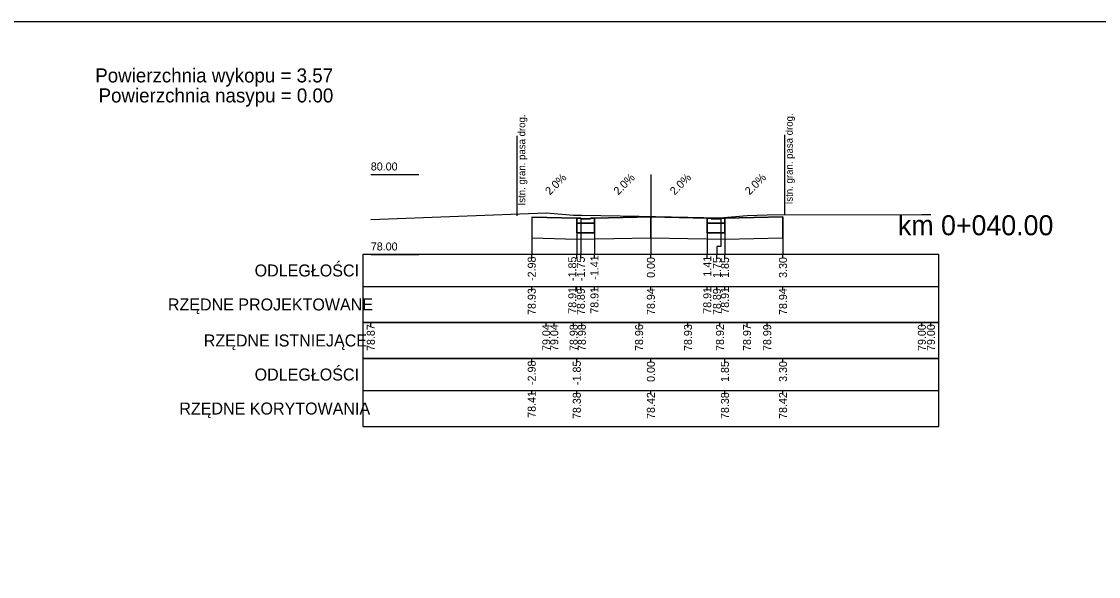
# Model space of a CAD drawing. Extents: x 7492871 to 7493499, y 5802964 to 5802992.
# Drawn here: x 7493013.99 to 7493040.9, y 5802978.41 to 5802992.28 of the extents above; entities that cross this region are included whole.
import ezdxf

# ---------------------------------------------------------------- set-up
doc = ezdxf.new("R2010")
doc.units = 0
for name, color, linetype in [('_wydruk', 7, 'Continuous'), ('d_pop_nasyp_opis', 7, 'Continuous'), ('d_pop_wykop_opis', 7, 'Continuous'), ('opisy_ramki_pop', 7, 'Continuous'), ('pop_comp_kostka', 7, 'Continuous'), ('pop_comp_lawa', 7, 'Continuous'), ('pop_comp_scieralna', 7, 'Continuous'), ('pop_granica_istn', 7, 'Continuous'), ('pop_opis', 7, 'Continuous'), ('pop_os', 7, 'Continuous'), ('pop_pikietaz', 7, 'Continuous'), ('pop_teren', 7, 'Continuous')]:
    doc.layers.add(name, color=color, linetype=linetype)

msp = doc.modelspace()

# ---------------------------------------------------------------- linework, layer by layer
msp.add_lwpolyline([(7493026.739, 5802987.391), (7493027.866, 5802987.368), (7493027.966, 5802987.368), (7493027.967, 5802987.348), (7493028.206, 5802987.348), (7493028.207, 5802987.368), (7493028.307, 5802987.368), (7493029.717, 5802987.397), (7493031.127, 5802987.368), (7493031.227, 5802987.368), (7493031.228, 5802987.348), (7493031.467, 5802987.348), (7493031.468, 5802987.368), (7493031.568, 5802987.368), (7493033.019, 5802987.397)])
at = {"layer": '_wydruk'}
msp.add_lwpolyline([(7492871.369, 5802992.281), (7493499.283, 5802992.281), (7493499.283, 5802963.881), (7492871.369, 5802963.881)], close=True, dxfattribs=at)
at = {"layer": 'opisy_ramki_pop'}
for points in [[(7493026.739, 5802986.871), (7493026.739, 5802986.659), (7493026.739, 5802986.659), (7493026.739, 5802986.459)], [(7493027.866, 5802986.839), (7493027.866, 5802986.659), (7493027.866, 5802986.659), (7493027.866, 5802986.459)], [(7493029.717, 5802986.877), (7493029.717, 5802986.659), (7493029.717, 5802986.659), (7493029.717, 5802986.459)], [(7493031.568, 5802986.839), (7493031.568, 5802986.659), (7493031.568, 5802986.659), (7493031.568, 5802986.459)], [(7493033.019, 5802986.877), (7493033.019, 5802986.659), (7493033.019, 5802986.659), (7493033.019, 5802986.459)]]:
    msp.add_lwpolyline(points, dxfattribs=at)
at = {"layer": 'pop_comp_kostka'}
for p, q in [((7493027.966, 5802987.368), (7493027.866, 5802987.368)), ((7493027.866, 5802987.368), (7493027.866, 5802987.238)), ((7493027.866, 5802987.238), (7493028.307, 5802987.238)), ((7493027.967, 5802987.348), (7493027.966, 5802987.368)), ((7493028.206, 5802987.348), (7493027.967, 5802987.348)), ((7493028.207, 5802987.368), (7493028.206, 5802987.348)), ((7493028.307, 5802987.368), (7493028.207, 5802987.368)), ((7493028.307, 5802987.238), (7493028.307, 5802987.368)), ((7493031.227, 5802987.368), (7493031.127, 5802987.368)), ((7493031.127, 5802987.368), (7493031.127, 5802987.238)), ((7493031.127, 5802987.238), (7493031.568, 5802987.238)), ((7493031.228, 5802987.348), (7493031.227, 5802987.368)), ((7493031.467, 5802987.348), (7493031.228, 5802987.348)), ((7493031.468, 5802987.368), (7493031.467, 5802987.348)), ((7493031.568, 5802987.368), (7493031.468, 5802987.368)), ((7493031.568, 5802987.238), (7493031.568, 5802987.368))]:
    msp.add_line(p, q, dxfattribs=at)
at = {"layer": 'pop_comp_lawa'}
for p, q in [((7493028.307, 5802987.238), (7493027.866, 5802987.238)), ((7493027.866, 5802987.238), (7493027.866, 5802986.998)), ((7493028.307, 5802986.998), (7493028.307, 5802987.238)), ((7493031.568, 5802987.238), (7493031.127, 5802987.238)), ((7493031.127, 5802987.238), (7493031.127, 5802986.998)), ((7493031.568, 5802986.998), (7493031.568, 5802987.238)), ((7493027.866, 5802986.998), (7493028.307, 5802986.998)), ((7493031.127, 5802986.998), (7493031.568, 5802986.998))]:
    msp.add_line(p, q, dxfattribs=at)
at = {"layer": 'pop_comp_scieralna'}
for p, q in [((7493027.866, 5802987.368), (7493026.739, 5802987.391)), ((7493026.739, 5802987.391), (7493026.739, 5802986.871)), ((7493027.866, 5802986.998), (7493027.866, 5802987.368)), ((7493029.717, 5802987.397), (7493028.307, 5802987.368)), ((7493028.307, 5802987.368), (7493028.307, 5802986.998)), ((7493029.717, 5802986.877), (7493029.717, 5802987.397)), ((7493031.127, 5802987.368), (7493029.717, 5802987.397)), ((7493029.717, 5802987.397), (7493029.717, 5802986.877)), ((7493031.127, 5802986.998), (7493031.127, 5802987.368)), ((7493033.019, 5802987.397), (7493031.568, 5802987.368)), ((7493031.568, 5802987.368), (7493031.568, 5802986.998)), ((7493033.019, 5802986.877), (7493033.019, 5802987.397)), ((7493028.307, 5802986.998), (7493027.866, 5802986.998)), ((7493031.568, 5802986.998), (7493031.127, 5802986.998)), ((7493026.739, 5802986.871), (7493027.866, 5802986.839)), ((7493027.866, 5802986.839), (7493029.717, 5802986.877)), ((7493029.717, 5802986.877), (7493031.568, 5802986.839)), ((7493031.568, 5802986.839), (7493033.019, 5802986.877))]:
    msp.add_line(p, q, dxfattribs=at)
at = {"layer": 'pop_granica_istn'}
for p, q in [((7493026.379, 5802987.923), (7493026.379, 5802989.423)), ((7493033.066, 5802987.949), (7493033.066, 5802989.449)), ((7493026.379, 5802987.423), (7493026.379, 5802987.923)), ((7493033.066, 5802987.449), (7493033.066, 5802987.949))]:
    msp.add_line(p, q, dxfattribs=at)
at = {"layer": 'pop_opis'}
for p, q in [((7493022.717, 5802988.459), (7493023.917, 5802988.459)), ((7493022.517, 5802986.459), (7493022.517, 5802984.759)), ((7493022.517, 5802986.459), (7493022.517, 5802984.759)), ((7493022.517, 5802986.459), (7493022.517, 5802984.759)), ((7493022.517, 5802986.459), (7493022.517, 5802984.759)), ((7493022.717, 5802986.459), (7493023.917, 5802986.459)), ((7493026.739, 5802986.359), (7493026.739, 5802986.459)), ((7493027.866, 5802986.359), (7493027.866, 5802986.459)), ((7493027.967, 5802986.359), (7493027.967, 5802986.459)), ((7493028.307, 5802986.359), (7493028.307, 5802986.459)), ((7493029.717, 5802986.359), (7493029.717, 5802986.459)), ((7493031.127, 5802986.359), (7493031.127, 5802986.459)), ((7493031.368, 5802986.359), (7493031.368, 5802986.459)), ((7493031.568, 5802986.359), (7493031.568, 5802986.459)), ((7493033.019, 5802986.359), (7493033.019, 5802986.459)), ((7493022.517, 5802985.659), (7493036.917, 5802985.659)), ((7493022.517, 5802985.659), (7493036.917, 5802985.659)), ((7493022.517, 5802985.659), (7493036.917, 5802985.659)), ((7493022.517, 5802985.659), (7493036.917, 5802985.659)), ((7493026.739, 5802985.559), (7493026.739, 5802985.659)), ((7493027.866, 5802985.559), (7493027.866, 5802985.659)), ((7493027.967, 5802985.559), (7493027.967, 5802985.659)), ((7493028.307, 5802985.559), (7493028.307, 5802985.659)), ((7493029.717, 5802985.559), (7493029.717, 5802985.659)), ((7493031.127, 5802985.559), (7493031.127, 5802985.659)), ((7493031.368, 5802985.559), (7493031.368, 5802985.659)), ((7493031.568, 5802985.559), (7493031.568, 5802985.659)), ((7493033.019, 5802985.559), (7493033.019, 5802985.659)), ((7493022.517, 5802984.759), (7493022.517, 5802983.859)), ((7493022.717, 5802984.659), (7493022.717, 5802984.759)), ((7493027.103, 5802984.659), (7493027.103, 5802984.759)), ((7493027.303, 5802984.659), (7493027.303, 5802984.759)), ((7493027.786, 5802984.659), (7493027.786, 5802984.759)), ((7493027.991, 5802984.659), (7493027.991, 5802984.759)), ((7493029.423, 5802984.659), (7493029.423, 5802984.759)), ((7493030.645, 5802984.659), (7493030.645, 5802984.759)), ((7493031.444, 5802984.659), (7493031.444, 5802984.759)), ((7493032.12, 5802984.659), (7493032.12, 5802984.759)), ((7493032.624, 5802984.659), (7493032.624, 5802984.759)), ((7493036.49, 5802984.659), (7493036.49, 5802984.759)), ((7493036.717, 5802984.659), (7493036.717, 5802984.759)), ((7493022.517, 5802983.859), (7493022.517, 5802982.159)), ((7493026.739, 5802983.759), (7493026.739, 5802983.859)), ((7493027.866, 5802983.759), (7493027.866, 5802983.859)), ((7493029.717, 5802983.759), (7493029.717, 5802983.859)), ((7493031.568, 5802983.759), (7493031.568, 5802983.859)), ((7493033.019, 5802983.759), (7493033.019, 5802983.859)), ((7493022.517, 5802983.059), (7493036.917, 5802983.059)), ((7493026.739, 5802982.959), (7493026.739, 5802983.059)), ((7493027.866, 5802982.959), (7493027.866, 5802983.059)), ((7493029.717, 5802982.959), (7493029.717, 5802983.059)), ((7493031.568, 5802982.959), (7493031.568, 5802983.059)), ((7493033.019, 5802982.959), (7493033.019, 5802983.059))]:
    msp.add_line(p, q, dxfattribs=at)
for points in [[(7493026.739, 5802987.391), (7493026.739, 5802986.659), (7493026.739, 5802986.659), (7493026.739, 5802986.459)], [(7493027.866, 5802987.368), (7493027.866, 5802986.659), (7493027.866, 5802986.659), (7493027.866, 5802986.459)], [(7493027.967, 5802987.348), (7493027.967, 5802986.659), (7493027.967, 5802986.659), (7493027.967, 5802986.459)], [(7493028.307, 5802987.368), (7493028.307, 5802986.659), (7493028.307, 5802986.659), (7493028.307, 5802986.459)], [(7493029.717, 5802987.397), (7493029.717, 5802986.659), (7493029.717, 5802986.659), (7493029.717, 5802986.459)], [(7493031.127, 5802987.368), (7493031.127, 5802986.659), (7493031.127, 5802986.659), (7493031.127, 5802986.459)], [(7493031.467, 5802987.348), (7493031.467, 5802986.659), (7493031.368, 5802986.659), (7493031.368, 5802986.459)], [(7493031.568, 5802987.368), (7493031.568, 5802986.659), (7493031.568, 5802986.659), (7493031.568, 5802986.459)], [(7493033.019, 5802987.397), (7493033.019, 5802986.659), (7493033.019, 5802986.659), (7493033.019, 5802986.459)]]:
    msp.add_lwpolyline(points, dxfattribs=at)
for points in [[(7493022.517, 5802986.459), (7493022.517, 5802984.759), (7493036.917, 5802984.759), (7493036.917, 5802986.459)], [(7493022.517, 5802986.459), (7493022.517, 5802984.759), (7493036.917, 5802984.759), (7493036.917, 5802986.459)], [(7493022.517, 5802986.459), (7493022.517, 5802984.759), (7493036.917, 5802984.759), (7493036.917, 5802986.459)], [(7493022.517, 5802986.459), (7493022.517, 5802984.759), (7493036.917, 5802984.759), (7493036.917, 5802986.459)], [(7493022.517, 5802984.759), (7493022.517, 5802983.859), (7493036.917, 5802983.859), (7493036.917, 5802984.759)], [(7493022.517, 5802983.859), (7493022.517, 5802982.159), (7493036.917, 5802982.159), (7493036.917, 5802983.859)]]:
    msp.add_lwpolyline(points, close=True, dxfattribs=at)
at = {"layer": 'pop_os'}
msp.add_line((7493029.717, 5802988.459), (7493029.717, 5802986.459), dxfattribs=at)
at = {"layer": 'pop_teren'}
msp.add_lwpolyline([(7493022.717, 5802987.333), (7493027.103, 5802987.501), (7493027.203, 5802987.495), (7493027.786, 5802987.438), (7493027.991, 5802987.44), (7493029.423, 5802987.416), (7493030.645, 5802987.389), (7493031.444, 5802987.376), (7493032.12, 5802987.434), (7493032.624, 5802987.452), (7493036.49, 5802987.461), (7493036.717, 5802987.457)], dxfattribs=at)

# ---------------------------------------------------------------- texts
at = {"layer": 'd_pop_nasyp_opis'}
msp.add_text('Powierzchnia nasypu = 0.00', height=0.35, dxfattribs=at).set_placement((7493015.912, 5802990.259))
at = {"layer": 'd_pop_wykop_opis'}
msp.add_text('Powierzchnia wykopu = 3.57', height=0.35, dxfattribs=at).set_placement((7493015.829, 5802990.759))
at = {"layer": 'pop_granica_istn'}
for p in [(7493026.577, 5802987.684), (7493033.264, 5802987.711)]:
    msp.add_text('Istn. gran. pasa drog.', height=0.18, rotation=90, dxfattribs=at).set_placement(p)
at = {"layer": 'pop_opis'}
for s, height, p in [('80.00', 0.2, (7493022.717, 5802988.559)), ('78.00', 0.2, (7493022.717, 5802986.559)), ('ODLEGŁOŚCI', 0.3, (7493019.813, 5802985.909)), ('ODLEGŁOŚCI', 0.3, (7493019.813, 5802985.909)), ('ODLEGŁOŚCI', 0.3, (7493019.813, 5802985.909)), ('ODLEGŁOŚCI', 0.3, (7493019.813, 5802985.909)), ('RZĘDNE PROJEKTOWANE', 0.3, (7493017.645, 5802985.059)), ('RZĘDNE PROJEKTOWANE', 0.3, (7493017.645, 5802985.059)), ('RZĘDNE PROJEKTOWANE', 0.3, (7493017.645, 5802985.059)), ('RZĘDNE PROJEKTOWANE', 0.3, (7493017.645, 5802985.059)), ('RZĘDNE ISTNIEJĄCE', 0.3, (7493018.542, 5802984.159)), ('ODLEGŁOŚCI', 0.3, (7493019.813, 5802983.309)), ('RZĘDNE KORYTOWANIA', 0.3, (7493017.931, 5802982.459))]:
    msp.add_text(s, height=height, dxfattribs=at).set_placement(p)
for s, rotation, p in [('2.0%', 45, (7493027.194, 5802987.93)), ('2.0%', 45, (7493028.903, 5802987.932)), ('2.0%', 45, (7493030.313, 5802987.932)), ('2.0%', 45, (7493032.185, 5802987.933)), ('-2.98', 90, (7493026.839, 5802985.797)), ('-1.85', 90, (7493027.853, 5802985.796)), ('-1.75', 90, (7493028.067, 5802985.796)), ('-1.41', 90, (7493028.407, 5802985.829)), ('0.00', 90, (7493029.817, 5802985.874)), ('1.41', 90, (7493031.227, 5802985.905)), ('1.75', 90, (7493031.468, 5802985.873)), ('1.85', 90, (7493031.668, 5802985.873)), ('3.30', 90, (7493033.119, 5802985.874)), ('78.93', 90, (7493026.839, 5802984.947)), ('78.91', 90, (7493027.853, 5802984.978)), ('78.89', 90, (7493028.067, 5802984.946)), ('78.91', 90, (7493028.407, 5802984.978)), ('78.94', 90, (7493029.817, 5802984.947)), ('78.91', 90, (7493031.227, 5802984.978)), ('78.89', 90, (7493031.468, 5802984.946)), ('78.91', 90, (7493031.668, 5802984.978)), ('78.94', 90, (7493033.119, 5802984.947)), ('78.87', 90, (7493022.817, 5802984.047)), ('79.04', 90, (7493027.203, 5802984.047)), ('79.04', 90, (7493027.403, 5802984.047)), ('78.98', 90, (7493027.886, 5802984.046)), ('78.98', 90, (7493028.091, 5802984.046)), ('78.96', 90, (7493029.523, 5802984.047)), ('78.93', 90, (7493030.745, 5802984.047)), ('78.92', 90, (7493031.544, 5802984.048)), ('78.97', 90, (7493032.22, 5802984.047)), ('78.99', 90, (7493032.724, 5802984.046)), ('79.00', 90, (7493036.59, 5802984.047)), ('79.00', 90, (7493036.817, 5802984.047)), ('-2.98', 90, (7493026.839, 5802983.197)), ('-1.85', 90, (7493027.966, 5802983.196)), ('0.00', 90, (7493029.817, 5802983.274)), ('1.85', 90, (7493031.668, 5802983.273)), ('3.30', 90, (7493033.119, 5802983.274)), ('78.41', 90, (7493026.839, 5802982.378)), ('78.38', 90, (7493027.966, 5802982.346)), ('78.42', 90, (7493029.817, 5802982.348)), ('78.38', 90, (7493031.668, 5802982.346)), ('78.42', 90, (7493033.119, 5802982.348))]:
    msp.add_text(s, height=0.2, rotation=rotation, dxfattribs=at).set_placement(p)
at = {"layer": 'pop_pikietaz'}
msp.add_text('km 0+040.00', height=0.5, dxfattribs=at).set_placement((7493035.893, 5802986.939))

doc.saveas('drawing.dxf')
